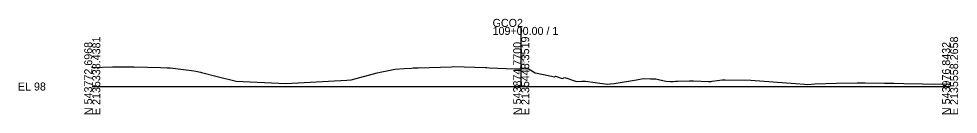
# Model space of a CAD drawing. Extents: x -14327 to 8886, y -10 to 39048.
# Drawn here: x 3974.3 to 4302.8, y 37990.3 to 38023.7 of the extents above; entities that cross this region are included whole.
import ezdxf

# ---------------------------------------------------------------- set-up
doc = ezdxf.new("R2010")
doc.units = 0
for name, color, linetype in [('RD_GPK_XS_Cell', 7, 'Continuous'), ('RD_XS_ExGround', 7, 'Continuous'), ('RD_XS_TX_Elev_EX', 7, 'Continuous')]:
    doc.layers.add(name, color=color, linetype=linetype)

msp = doc.modelspace()

# ---------------------------------------------------------------- linework, layer by layer
at = {"layer": 'RD_GPK_XS_Cell'}
for p, q in [((4150, 38000), (4150, 38020.85)), ((4000, 38000), (4150, 38000)), ((4150, 38000), (4300, 38000))]:
    msp.add_line(p, q, dxfattribs=at)
at = {"layer": 'RD_XS_ExGround'}
for p, q in [((4000, 38006.65), (4007.08, 38006.83)), ((4007.08, 38006.83), (4011.55, 38006.93)), ((4011.55, 38006.93), (4014.61, 38006.86)), ((4014.61, 38006.86), (4023.98, 38006.6)), ((4023.98, 38006.6), (4026.15, 38006.5)), ((4026.15, 38006.5), (4027.26, 38006.48)), ((4027.26, 38006.48), (4034.69, 38005.6)), ((4034.69, 38005.6), (4036.23, 38005.4)), ((4036.23, 38005.4), (4037.84, 38005.01)), ((4037.84, 38005.01), (4038.16, 38004.93)), ((4038.16, 38004.93), (4043.69, 38003.55)), ((4090.56, 38002.34), (4099.67, 38004.77)), ((4099.67, 38004.77), (4100.64, 38005.03)), ((4100.64, 38005.03), (4105.93, 38006.09)), ((4105.93, 38006.09), (4109.11, 38006.3)), ((4109.11, 38006.3), (4111.61, 38006.47)), ((4111.61, 38006.47), (4112.2, 38006.5)), ((4112.2, 38006.5), (4113.99, 38006.58)), ((4113.99, 38006.58), (4125.6, 38006.93)), ((4125.6, 38006.93), (4126.34, 38006.95)), ((4126.34, 38006.95), (4137.55, 38006.62)), ((4137.55, 38006.62), (4138.04, 38006.6)), ((4138.04, 38006.6), (4138.89, 38006.57)), ((4138.89, 38006.57), (4147.68, 38006.22)), ((4147.68, 38006.22), (4150, 38006.24)), ((4150, 38006.24), (4151.49, 38006.25)), ((4151.49, 38006.25), (4152.47, 38006.28)), ((4152.47, 38006.28), (4154.3, 38005.14)), ((4154.3, 38005.14), (4154.86, 38004.81)), ((4154.86, 38004.81), (4155.59, 38004.67)), ((4155.59, 38004.67), (4161.71, 38003.36)), ((4043.69, 38003.55), (4050.35, 38001.89)), ((4050.35, 38001.89), (4055.17, 38001.69)), ((4055.17, 38001.69), (4067.75, 38001.03)), ((4067.75, 38001.03), (4089, 38002.27)), ((4089, 38002.27), (4090.56, 38002.34)), ((4161.71, 38003.36), (4162.02, 38003.63)), ((4162.02, 38003.63), (4164.34, 38002.8)), ((4164.34, 38002.8), (4165.3, 38003.13)), ((4165.3, 38003.13), (4169.33, 38001.8)), ((4169.33, 38001.8), (4171.25, 38001.82)), ((4171.25, 38001.82), (4172.48, 38001.84)), ((4172.48, 38001.84), (4175.83, 38001.46)), ((4175.83, 38001.46), (4180.04, 38000.83)), ((4182.48, 38001.02), (4190.3, 38002.3)), ((4190.3, 38002.3), (4192.61, 38002.78)), ((4192.61, 38002.78), (4195.25, 38002.66)), ((4195.25, 38002.66), (4197.1, 38002.65)), ((4197.1, 38002.65), (4198.01, 38002.43)), ((4198.01, 38002.43), (4200.64, 38001.85)), ((4200.64, 38001.85), (4202.28, 38001.81)), ((4202.28, 38001.81), (4202.87, 38001.77)), ((4202.87, 38001.77), (4203.19, 38001.79)), ((4203.19, 38001.79), (4203.95, 38001.82)), ((4203.95, 38001.82), (4204.65, 38001.84)), ((4204.65, 38001.84), (4208.92, 38001.97)), ((4208.92, 38001.97), (4210.26, 38002)), ((4210.26, 38002), (4215.49, 38001.81)), ((4215.49, 38001.81), (4216.46, 38001.77)), ((4216.46, 38001.77), (4216.84, 38001.84)), ((4216.84, 38001.84), (4220.27, 38002.36)), ((4220.27, 38002.36), (4221.33, 38002.35)), ((4221.33, 38002.35), (4230.28, 38002.18)), ((4230.28, 38002.18), (4245.94, 38001.08)), ((4180.04, 38000.83), (4181.29, 38000.91)), ((4181.29, 38000.91), (4182.48, 38001.02)), ((4245.94, 38001.08), (4249.14, 38000.79)), ((4249.14, 38000.79), (4250.29, 38000.76)), ((4250.29, 38000.76), (4252.7, 38000.88)), ((4252.7, 38000.88), (4260.3, 38001.21)), ((4260.3, 38001.21), (4267.54, 38001.26)), ((4267.54, 38001.26), (4270.3, 38001.23)), ((4270.3, 38001.23), (4277.08, 38001.18)), ((4277.08, 38001.18), (4280.31, 38001.13)), ((4280.31, 38001.13), (4283.82, 38001.11)), ((4283.82, 38001.11), (4290.32, 38000.92)), ((4290.32, 38000.92), (4294.46, 38000.87)), ((4294.46, 38000.87), (4300, 38000.88))]:
    msp.add_line(p, q, dxfattribs=at)

# ---------------------------------------------------------------- texts
at = {"layer": 'RD_GPK_XS_Cell'}
for s, p in [('GCO2', (4140, 38020.85)), ('109+00.00 / 1', (4140, 38018.05)), ('EL 98', (3974, 37998.6))]:
    msp.add_text(s, height=2.8, dxfattribs=at).set_placement(p)
for s, p in [('N 543772.6968', (4000, 37990)), ('E 2135338.4381', (4002.8, 37990)), ('N 543874.7700', (4150, 37990)), ('E 2135448.3519', (4152.8, 37990)), ('N 543976.8432', (4300, 37990)), ('E 2135558.2658', (4302.8, 37990))]:
    msp.add_text(s, height=2.8, rotation=90, dxfattribs=at).set_placement(p)
at = {"layer": 'RD_XS_TX_Elev_EX'}
msp.add_text('104.24', height=1, rotation=90, dxfattribs=at).set_placement((4151.25, 38007.24))

doc.saveas('drawing.dxf')
